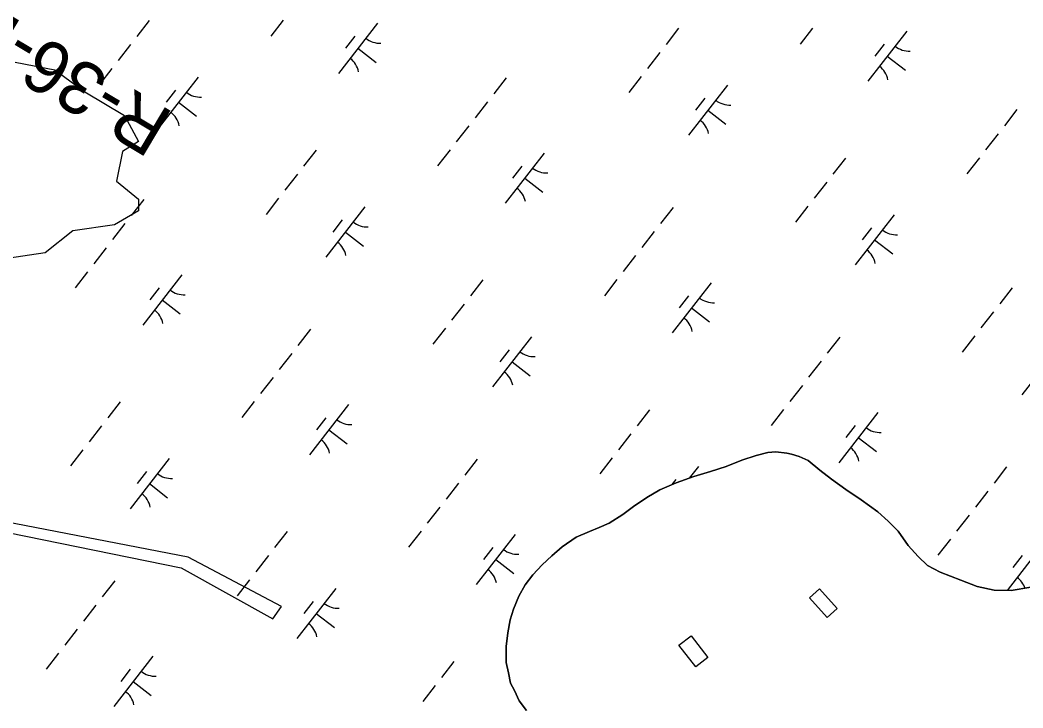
# Model space of a CAD drawing. Extents: x 3888273 to 3909528, y 158682 to 181032.
# Drawn here: x 3900792 to 3901581, y 167398 to 167939 of the extents above; entities that cross this region are included whole.
import ezdxf

# ---------------------------------------------------------------- set-up
doc = ezdxf.new("R2010")
doc.units = 0
for name, color, linetype in [('V-CHAN-DOCK', 7, 'Continuous'), ('V-RIVR-EDGE', 7, 'Continuous'), ('V-RIVR-RANG-IDEN', 7, 'Continuous'), ('V-TOPO-SHOR', 7, 'Continuous'), ('V-WETL-SWMP', 7, 'Continuous')]:
    doc.layers.add(name, color=color, linetype=linetype)

msp = doc.modelspace()

# ---------------------------------------------------------------- linework, layer by layer
at = {"layer": 'V-CHAN-DOCK'}
for points in [[(3900564.15, 167580.27), (3900918.34, 167508.04), (3900990.57, 167467.76), (3900997.51, 167477.48), (3900923.9, 167516.38), (3900564.15, 167585.82)], [(3901420.97, 167491.53), (3901434.87, 167476.08), (3901427.02, 167469.02), (3901413.12, 167484.46)], [(3901319.81, 167454.46), (3901332.93, 167437.47), (3901323.44, 167430.13), (3901310.31, 167447.12)]]:
    msp.add_lwpolyline(points, close=True, dxfattribs=at)
at = {"layer": 'V-RIVR-EDGE'}
msp.add_lwpolyline([(3900787.82, 167906.12), (3900819.09, 167899.87), (3900842.53, 167882.67), (3900873.79, 167863.92), (3900884.73, 167843.6), (3900872.23, 167835.78), (3900867.54, 167812.34), (3900884.73, 167798.27), (3900884.73, 167788.89), (3900865.98, 167777.95), (3900833.15, 167773.26), (3900811.27, 167756.06), (3900781.57, 167751.37)], dxfattribs=at)
at = {"layer": 'V-TOPO-SHOR'}
msp.add_lwpolyline([(3901190.33, 167395.72), (3901184.41, 167403.41), (3901180.81, 167411.52), (3901177.64, 167417.3), (3901175.98, 167425.43), (3901174.33, 167433.56), (3901174.18, 167445.98), (3901175.59, 167456.87), (3901177.41, 167466.98), (3901180.02, 167475.55), (3901184.16, 167485.7), (3901189.1, 167494.69), (3901195.21, 167502.53), (3901202.49, 167510.38), (3901210.16, 167517.46), (3901218.23, 167524.55), (3901229.39, 167532.07), (3901239.82, 167536.47), (3901247.54, 167539.67), (3901255.26, 167543.26), (3901266.04, 167549.99), (3901274.51, 167556.31), (3901284.9, 167563.42), (3901295.3, 167569.38), (3901308.04, 167574.97), (3901321.96, 167579.8), (3901335.11, 167583.85), (3901347.48, 167587.88), (3901359.84, 167592.69), (3901371.05, 167596.32), (3901380.34, 167598.77), (3901386.54, 167599.23), (3901395.1, 167598.18), (3901398.99, 167597.45), (3901404.83, 167595.58), (3901411.86, 167592.56), (3901421.27, 167584.91), (3901430.29, 167577.65), (3901441.64, 167569.64), (3901453.78, 167561.64), (3901466.71, 167552.1), (3901474.95, 167544.82), (3901482.81, 167536.77), (3901490.71, 167525.61), (3901498.59, 167516.78), (3901506.05, 167509.89), (3901515.82, 167504.57), (3901532.2, 167498.18), (3901545.07, 167493.29), (3901558.31, 167490.35), (3901571.9, 167490.13), (3901587.39, 167492.65)], dxfattribs=at)
at = {"layer": 'V-WETL-SWMP'}
for p, q in [((3900893.37, 167938.88), (3900883.54, 167926.25)), ((3900998.83, 167939.12), (3900989, 167926.49)), ((3901072.97, 167936.65), (3901042.27, 167897.18)), ((3901310.03, 167932.65), (3901300.21, 167920.02)), ((3901415.5, 167932.89), (3901405.67, 167920.26)), ((3901489.64, 167930.42), (3901458.93, 167890.96)), ((3901055.21, 167926.39), (3901047.85, 167916.92)), ((3900878.63, 167919.93), (3900868.8, 167907.31)), ((3901057.62, 167916.91), (3901071.83, 167905.86)), ((3901471.88, 167920.16), (3901464.51, 167910.69)), ((3901295.29, 167913.71), (3901285.47, 167901.08)), ((3901474.29, 167910.69), (3901488.49, 167899.63)), ((3900863.89, 167900.99), (3900854.06, 167888.36)), ((3900931.73, 167894.2), (3900901.03, 167854.73)), ((3901174.32, 167893.8), (3901164.5, 167881.17)), ((3901280.56, 167894.77), (3901270.73, 167882.14)), ((3900913.97, 167883.94), (3900906.6, 167874.47)), ((3901348.4, 167887.97), (3901317.69, 167848.51)), ((3901330.64, 167877.71), (3901323.27, 167868.24)), ((3900916.38, 167874.47), (3900930.58, 167863.41)), ((3901159.58, 167874.86), (3901149.76, 167862.23)), ((3901333.05, 167868.24), (3901347.25, 167857.19)), ((3901576.25, 167868.63), (3901566.43, 167856)), ((3901144.85, 167855.92), (3901135.02, 167843.29)), ((3901561.51, 167849.69), (3901551.69, 167837.06)), ((3901024.65, 167836.73), (3901014.82, 167824.1)), ((3901130.11, 167836.97), (3901120.28, 167824.35)), ((3901204.25, 167834.5), (3901173.55, 167795.04)), ((3901441.31, 167830.51), (3901431.49, 167817.88)), ((3901546.78, 167830.75), (3901536.95, 167818.12)), ((3901186.49, 167824.24), (3901179.13, 167814.77)), ((3901009.91, 167817.79), (3901000.08, 167805.16)), ((3901188.9, 167814.77), (3901203.11, 167803.72)), ((3901426.58, 167811.56), (3901416.75, 167798.94)), ((3900888.94, 167797.88), (3900879.11, 167785.25)), ((3900995.17, 167798.85), (3900985.34, 167786.22)), ((3901063.01, 167792.05), (3901032.31, 167752.59)), ((3901305.6, 167791.65), (3901295.78, 167779.03)), ((3901411.84, 167792.62), (3901402.01, 167779.99)), ((3901045.25, 167781.79), (3901037.88, 167772.32)), ((3901479.68, 167785.83), (3901448.97, 167746.36)), ((3900874.2, 167778.94), (3900864.37, 167766.31)), ((3901047.66, 167772.32), (3901061.87, 167761.27)), ((3901290.87, 167772.71), (3901281.04, 167760.08)), ((3901461.92, 167775.57), (3901454.55, 167766.1)), ((3901464.33, 167766.09), (3901478.53, 167755.04)), ((3900859.46, 167760), (3900849.63, 167747.37)), ((3901276.13, 167753.77), (3901266.3, 167741.14)), ((3900844.72, 167741.05), (3900834.9, 167728.43)), ((3900918.87, 167738.58), (3900888.16, 167699.12)), ((3901155.93, 167734.59), (3901146.1, 167721.96)), ((3901261.39, 167734.83), (3901251.56, 167722.2)), ((3900901.11, 167728.32), (3900893.74, 167718.85)), ((3901335.53, 167732.36), (3901304.83, 167692.89)), ((3901572.59, 167728.36), (3901562.77, 167715.73)), ((3900903.51, 167718.85), (3900917.72, 167707.8)), ((3901317.78, 167722.1), (3901310.41, 167712.63)), ((3901141.19, 167715.64), (3901131.36, 167703.02)), ((3901320.18, 167712.62), (3901334.39, 167701.57)), ((3901557.86, 167709.42), (3901548.03, 167696.79)), ((3901020.22, 167695.74), (3901010.39, 167683.11)), ((3901126.45, 167696.7), (3901116.63, 167684.07)), ((3901194.29, 167689.91), (3901163.59, 167650.44)), ((3901436.88, 167689.51), (3901427.06, 167676.88)), ((3901543.12, 167690.48), (3901533.29, 167677.85)), ((3901176.53, 167679.65), (3901169.17, 167670.18)), ((3901610.96, 167683.68), (3901580.25, 167644.22)), ((3901005.48, 167676.79), (3900995.65, 167664.17)), ((3901178.94, 167670.18), (3901193.15, 167659.12)), ((3901422.15, 167670.57), (3901412.32, 167657.94)), ((3900990.74, 167657.85), (3900980.92, 167645.22)), ((3901407.41, 167651.63), (3901397.58, 167639)), ((3900870.54, 167638.67), (3900860.71, 167626.04)), ((3900976, 167638.91), (3900966.18, 167626.28)), ((3901050.15, 167636.44), (3901019.44, 167596.97)), ((3901287.21, 167632.44), (3901277.38, 167619.81)), ((3901392.67, 167632.68), (3901382.84, 167620.06)), ((3901466.81, 167630.21), (3901436.11, 167590.75)), ((3901032.39, 167626.18), (3901025.02, 167616.71)), ((3900855.8, 167619.73), (3900845.98, 167607.1)), ((3901034.79, 167616.71), (3901049, 167605.65)), ((3901449.06, 167619.95), (3901441.69, 167610.48)), ((3901272.47, 167613.5), (3901262.64, 167600.87)), ((3901451.46, 167610.48), (3901465.67, 167599.43)), ((3900841.06, 167600.78), (3900831.24, 167588.16)), ((3901380.34, 167598.77), (3901371.05, 167596.32)), ((3901386.54, 167599.23), (3901380.34, 167598.77)), ((3901395.1, 167598.18), (3901386.54, 167599.23)), ((3900908.9, 167593.99), (3900878.2, 167554.53)), ((3901151.5, 167593.59), (3901141.67, 167580.96)), ((3901257.73, 167594.56), (3901247.91, 167581.93)), ((3901359.84, 167592.69), (3901347.48, 167587.88)), ((3901371.05, 167596.32), (3901359.84, 167592.69)), ((3901398.99, 167597.45), (3901395.1, 167598.18)), ((3901404.83, 167595.58), (3901398.99, 167597.45)), ((3901411.86, 167592.56), (3901404.83, 167595.58)), ((3901421.27, 167584.92), (3901411.86, 167592.56)), ((3900891.15, 167583.73), (3900883.78, 167574.26)), ((3901325.57, 167587.76), (3901318.42, 167578.57)), ((3901335.11, 167583.84), (3901321.96, 167579.8)), ((3901347.48, 167587.88), (3901335.11, 167583.84)), ((3901430.29, 167577.65), (3901421.27, 167584.92)), ((3901568.16, 167587.36), (3901558.34, 167574.74)), ((3901308.04, 167574.97), (3901295.31, 167569.38)), ((3901307.82, 167577.5), (3901304.7, 167573.5)), ((3901321.96, 167579.8), (3901308.04, 167574.97)), ((3901441.64, 167569.64), (3901430.29, 167577.65)), ((3900893.55, 167574.26), (3900907.76, 167563.2)), ((3901136.76, 167574.65), (3901126.93, 167562.02)), ((3901295.31, 167569.38), (3901284.9, 167563.42)), ((3901453.78, 167561.64), (3901441.64, 167569.64)), ((3901553.43, 167568.42), (3901543.6, 167555.79)), ((3901284.9, 167563.42), (3901274.51, 167556.31)), ((3901466.71, 167552.1), (3901453.78, 167561.64)), ((3901122.02, 167555.71), (3901112.2, 167543.08)), ((3901274.51, 167556.31), (3901266.04, 167549.99)), ((3901474.95, 167544.82), (3901466.71, 167552.1)), ((3901266.04, 167549.99), (3901255.26, 167543.26)), ((3901482.81, 167536.77), (3901474.95, 167544.82)), ((3901538.69, 167549.48), (3901528.86, 167536.85)), ((3901001.82, 167536.52), (3900992, 167523.89)), ((3901107.28, 167536.77), (3901097.46, 167524.14)), ((3901239.82, 167536.47), (3901229.39, 167532.07)), ((3901247.54, 167539.67), (3901239.82, 167536.47)), ((3901255.26, 167543.26), (3901247.54, 167539.67)), ((3901490.71, 167525.61), (3901482.81, 167536.77)), ((3901181.43, 167534.29), (3901150.72, 167494.83)), ((3901229.39, 167532.07), (3901218.23, 167524.55)), ((3901523.95, 167530.54), (3901514.13, 167517.91)), ((3901598.09, 167528.07), (3901568.62, 167490.18)), ((3901163.67, 167524.03), (3901156.3, 167514.56)), ((3901218.23, 167524.55), (3901210.16, 167517.46)), ((3901498.59, 167516.78), (3901490.71, 167525.61)), ((3900987.08, 167517.58), (3900977.26, 167504.95)), ((3901166.07, 167514.56), (3901180.28, 167503.51)), ((3901210.16, 167517.46), (3901202.49, 167510.38)), ((3901506.05, 167509.89), (3901498.59, 167516.78)), ((3901580.34, 167517.81), (3901572.97, 167508.34)), ((3901202.49, 167510.38), (3901195.21, 167502.53)), ((3901515.82, 167504.57), (3901506.05, 167509.89)), ((3901532.2, 167498.18), (3901515.82, 167504.57)), ((3900866.11, 167497.67), (3900856.29, 167485.04)), ((3900972.34, 167498.64), (3900962.52, 167486.01)), ((3901195.21, 167502.53), (3901189.1, 167494.69)), ((3901545.07, 167493.29), (3901532.2, 167498.18)), ((3901040.19, 167491.84), (3901009.48, 167452.38)), ((3901189.1, 167494.69), (3901184.16, 167485.7)), ((3901558.31, 167490.35), (3901545.07, 167493.29)), ((3901571.9, 167490.13), (3901558.31, 167490.35)), ((3901587.39, 167492.65), (3901571.9, 167490.13)), ((3901022.43, 167481.59), (3901015.06, 167472.11)), ((3901184.16, 167485.7), (3901180.02, 167475.55)), ((3900851.37, 167478.73), (3900841.55, 167466.1)), ((3901180.02, 167475.55), (3901177.41, 167466.98)), ((3901024.83, 167472.11), (3901039.04, 167461.06)), ((3901177.41, 167466.98), (3901175.59, 167456.87)), ((3900836.63, 167459.79), (3900826.81, 167447.16)), ((3901175.59, 167456.87), (3901174.18, 167445.98)), ((3900821.9, 167440.85), (3900812.07, 167428.22)), ((3901174.18, 167445.98), (3901174.33, 167433.56)), ((3900896.04, 167438.37), (3900865.34, 167398.91)), ((3901133.1, 167434.38), (3901123.28, 167421.75)), ((3901174.33, 167433.56), (3901175.98, 167425.43)), ((3900878.28, 167428.12), (3900870.91, 167418.64)), ((3901175.98, 167425.43), (3901177.64, 167417.3)), ((3900880.69, 167418.64), (3900894.89, 167407.59)), ((3901177.64, 167417.3), (3901180.81, 167411.52)), ((3901118.36, 167415.44), (3901108.54, 167402.81)), ((3901180.81, 167411.52), (3901184.41, 167403.41)), ((3901184.41, 167403.41), (3901190.33, 167395.72))]:
    msp.add_line(p, q, dxfattribs=at)
for centre, start, end in [((3901074.77, 167938.57), 231.34298, 272.88664), ((3901491.44, 167932.34), 231.34298, 272.88664), ((3901040.84, 167894.97), 11.34298, 52.88663), ((3901457.51, 167888.74), 11.34298, 52.88663), ((3900933.53, 167896.12), 231.34298, 272.88664), ((3901350.19, 167889.89), 231.34298, 272.88664), ((3900899.6, 167852.52), 11.34298, 52.88663), ((3901316.27, 167846.29), 11.34298, 52.88663), ((3901206.05, 167836.42), 231.34298, 272.88664), ((3901172.13, 167792.82), 11.34298, 52.88663), ((3901064.81, 167793.97), 231.34298, 272.88664), ((3901481.48, 167787.75), 231.34298, 272.88664), ((3901030.88, 167750.37), 11.34298, 52.88663), ((3901447.55, 167744.15), 11.34298, 52.88663), ((3900920.66, 167740.5), 231.34298, 272.88664), ((3901337.33, 167734.28), 231.34298, 272.88664), ((3900886.74, 167696.9), 11.34298, 52.88663), ((3901303.41, 167690.68), 11.34298, 52.88663), ((3901196.09, 167691.83), 231.34298, 272.88664), ((3901162.16, 167648.23), 11.34298, 52.88663), ((3901051.94, 167638.36), 231.34298, 272.88664), ((3901468.61, 167632.13), 231.34298, 272.88664), ((3901018.02, 167594.76), 11.34298, 52.88663), ((3901434.69, 167588.53), 11.34298, 52.88663), ((3900910.7, 167595.91), 231.34298, 272.88664), ((3900876.78, 167552.31), 11.34298, 52.88663), ((3901183.22, 167536.22), 231.34298, 272.88664), ((3901149.3, 167492.62), 11.34298, 52.88663), ((3901565.97, 167486.39), 18.19482, 52.88663), ((3901041.98, 167493.77), 231.34298, 272.88664), ((3901008.06, 167450.17), 11.34298, 52.88663), ((3900897.84, 167440.3), 231.34298, 272.88664), ((3900863.91, 167396.7), 11.34298, 52.88663)]:
    msp.add_arc(centre, 17.62, start, end, dxfattribs=at)

# ---------------------------------------------------------------- texts
at = {"layer": 'V-RIVR-RANG-IDEN'}
msp.add_text('R-36-D', height=41.5, rotation=149.18579, dxfattribs=at).set_placement((3900913.87, 167865.58))

doc.saveas('drawing.dxf')
